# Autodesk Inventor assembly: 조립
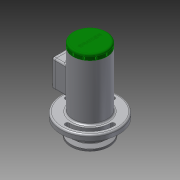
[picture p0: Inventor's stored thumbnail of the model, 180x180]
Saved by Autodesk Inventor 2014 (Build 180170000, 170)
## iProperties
Created: 2017-05
Part Number: 조립
Document SubType Name: Assembly
Designer: Administrator
Author: Administrator
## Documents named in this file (20)
- C:\Users\Administrator\Desktop\새 폴더\470508V1009\조립.iam
- C:\Users\Administrator\Desktop\새 폴더\470508V1009\1-본체.ipt
- C:\Users\Administrator\Desktop\새 폴더\470508V1009\V-벨트풀리.ipt
- C:\Users\Administrator\Desktop\새 폴더\470508V1009\너트 M10.ipt
- C:\Users\Administrator\Desktop\새 폴더\470508V1009\멈춤링 15 x 1.ipt
- C:\Users\Administrator\Desktop\새 폴더\470508V1009\멈춤링 35x1.6.ipt
- C:\Users\Administrator\Desktop\새 폴더\470508V1009\베어링 15 x 35 x 11.ipt
- C:\Users\Administrator\Desktop\새 폴더\470508V1009\볼트 M4 x 10.ipt
- C:\Users\Administrator\Desktop\새 폴더\470508V1009\부시1.ipt
- C:\Users\Administrator\Desktop\새 폴더\470508V1009\부시2.ipt
- C:\Users\Administrator\Desktop\새 폴더\470508V1009\사이드 커버.ipt
- 사이드 커버.ipt
- C:\Users\Administrator\Desktop\새 폴더\470508V1009\십자볼트 M3 x 10.ipt
- C:\Users\Administrator\Desktop\새 폴더\470508V1009\오일 실 15 25 7.ipt
- C:\Users\Administrator\Desktop\새 폴더\470508V1009\와셔 3x6.ipt
- C:\Users\Administrator\Desktop\새 폴더\470508V1009\와셔 4x16.ipt
- C:\Users\Administrator\Desktop\새 폴더\470508V1009\와셔 10x21.ipt
- C:\Users\Administrator\Desktop\새 폴더\470508V1009\축.ipt
- C:\Users\Administrator\Desktop\새 폴더\470508V1009\키 4 x 4 x 18.ipt
- C:\Users\Administrator\Desktop\새 폴더\470508V1009\탑 커버.ipt
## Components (3 placed, 3 different names)
1. 1-본체:1 — Mate:1, Mate:2, Mate:3, Mate:4, Mate:5, Mate:6, Mate:7, Mate:8, Mate:9, Mate:11, Mate:12, Mate:14, Mate:25, Mate:26, Mate:27, Mate:45
2. V-벨트풀리:1 — Mate:18, Mate:19, Mate:20
3. ISO 4017 M4 x 10:1 — Mate:21, Mate:24, Mate:43
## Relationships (22: Mate 22)
- Mate:1: 1-본체:1
- Mate:2: 1-본체:1
- Mate:3: 1-본체:1
- Mate:4: 1-본체:1
- Mate:5: 1-본체:1
- Mate:6: 1-본체:1
- Mate:7: 1-본체:1
- Mate:8: 1-본체:1
- Mate:9: 1-본체:1
- Mate:11: 1-본체:1
- Mate:12: 1-본체:1
- Mate:14: 1-본체:1
- Mate:18: V-벨트풀리:1
- Mate:19: V-벨트풀리:1
- Mate:20: V-벨트풀리:1
- Mate:21: ISO 4017 M4 x 10:1
- Mate:24: ISO 4017 M4 x 10:1
- Mate:25: 1-본체:1
- Mate:26: 1-본체:1
- Mate:27: 1-본체:1
- Mate:43: ISO 4017 M4 x 10:1
- Mate:45: 1-본체:1
